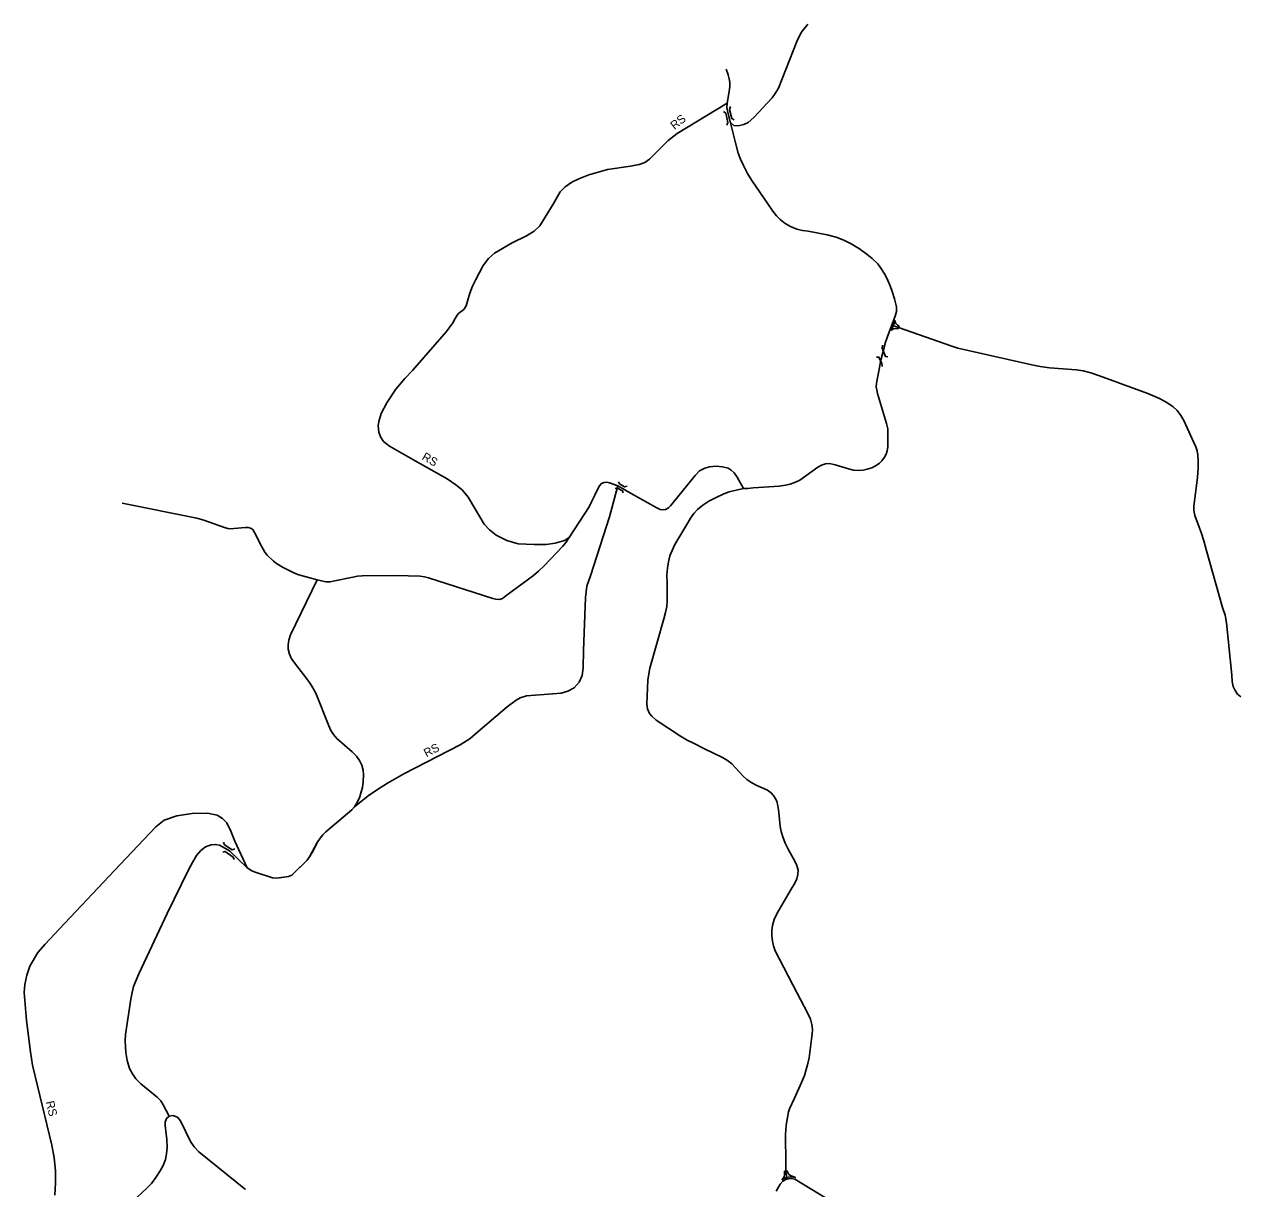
# Model space of a CAD drawing. Extents: x -546703 to -534152, y -1046534 to -1035676.
# Drawn here: x -544992 to -543548, y -1039069 to -1037684 of the extents above; entities that cross this region are included whole.
import ezdxf

# ---------------------------------------------------------------- set-up
doc = ezdxf.new("R2010")
doc.units = 0
for name, color, linetype in [('Vrstva 11', 7, 'Continuous'), ('Vrstva 22', 7, 'Continuous'), ('Vrstva 8', 7, 'Continuous')]:
    doc.layers.add(name, color=color, linetype=linetype)

msp = doc.modelspace()

# ---------------------------------------------------------------- linework, layer by layer
at = {"layer": 'Vrstva 11'}
for points in [[(-544157.7, -1037737), (-544155.1, -1037743.6), (-544153.8, -1037748.4), (-544153.2, -1037752.7), (-544153.2, -1037757.6), (-544154, -1037763.6), (-544156.5, -1037777.6), (-544156.7, -1037782.4), (-544156, -1037786.4), (-544146.4, -1037824.7), (-544143.3, -1037837), (-544140.5, -1037844.1), (-544136.9, -1037851.4), (-544132.1, -1037861.2), (-544127, -1037869.5), (-544108.1, -1037897.3), (-544102.2, -1037905.9), (-544097.7, -1037911.4), (-544093.1, -1037915.9), (-544087.2, -1037920.5), (-544081.2, -1037924.1), (-544073.6, -1037927.1), (-544066.8, -1037928.8), (-544060, -1037929.7), (-544037.5, -1037933.9), (-544026.5, -1037936.7), (-544017.5, -1037940.3), (-544009, -1037944.7), (-543999.1, -1037950.7), (-543989.9, -1037957.4), (-543984, -1037962.2), (-543977.3, -1037968.7), (-543973.5, -1037973.8), (-543968.5, -1037981.6), (-543965.1, -1037988.5), (-543962.5, -1037994.9), (-543960, -1038001.6), (-543957.5, -1038010), (-543955, -1038019.5), (-543955, -1038025.4), (-543956.4, -1038030.9), (-543964.3, -1038052), (-543967.9, -1038061.8), (-543973.8, -1038084.9), (-543975.2, -1038091.9), (-543978.7, -1038110.3), (-543979, -1038115), (-543978.3, -1038118.7), (-543977.5, -1038122.7), (-543966.9, -1038158.4), (-543965.4, -1038164.8), (-543965.1, -1038170.6), (-543965.1, -1038176.8), (-543965.3, -1038186.8), (-543966, -1038190.8), (-543967.4, -1038194.8), (-543969.2, -1038198.4), (-543972.3, -1038202.8), (-543975.2, -1038205.7), (-543979.2, -1038208.4), (-543984.2, -1038211.1), (-543989.9, -1038212.9), (-543994.4, -1038213.8), (-544000.2, -1038214.3), (-544006.2, -1038214), (-544012, -1038212.5), (-544028, -1038207.5), (-544034.5, -1038206.2), (-544039.3, -1038206.6), (-544044.2, -1038208), (-544048.3, -1038210.3), (-544069.8, -1038226), (-544074.9, -1038228.3), (-544081.3, -1038230.6), (-544086.9, -1038232), (-544094.6, -1038233), (-544125.6, -1038235.1), (-544131.9, -1038235.6), (-544137.1, -1038235.9), (-544145.6, -1038237.6), (-544154.1, -1038239.9), (-544160.2, -1038242.2), (-544170.2, -1038246.8), (-544178.1, -1038250.9), (-544185.4, -1038255.5), (-544191.7, -1038260.6), (-544196, -1038265.7), (-544200.1, -1038271.2), (-544203.2, -1038276.8), (-544218.4, -1038302.6), (-544221.9, -1038309.6), (-544224.4, -1038316), (-544226.2, -1038323), (-544227.4, -1038330.4), (-544228.1, -1038338.5), (-544227.8, -1038348.8), (-544227.5, -1038369.7), (-544228.1, -1038376), (-544229.5, -1038383.2), (-544231.7, -1038390.9), (-544248.4, -1038449.6), (-544249.6, -1038456.2), (-544250.5, -1038463.8), (-544251.2, -1038473.5), (-544251.7, -1038492.3), (-544250.9, -1038497.9), (-544248.7, -1038503.3), (-544245.8, -1038506.6), (-544240.6, -1038511.2), (-544212, -1038530.3), (-544203.8, -1038535.1), (-544196.5, -1038538.9), (-544183.4, -1038545.4), (-544162, -1038555.7), (-544156, -1038559.2), (-544150.8, -1038563.4), (-544146.4, -1038568), (-544137.5, -1038578.1), (-544133, -1038581.8), (-544127, -1038586), (-544121, -1038589.1), (-544108.3, -1038594.8), (-544103.8, -1038598.3), (-544100.3, -1038602.3), (-544097.3, -1038607.7), (-544096, -1038613.2), (-544095.3, -1038617.9), (-544094.4, -1038625), (-544093.4, -1038637.8), (-544092.2, -1038643.9), (-544090.1, -1038650.3), (-544087.2, -1038657.7), (-544083.3, -1038665.7), (-544075.8, -1038679.3), (-544073.5, -1038684.3), (-544072, -1038689.7), (-544072.2, -1038694.9), (-544073.6, -1038700), (-544075.9, -1038705.3), (-544080.1, -1038712.3), (-544097, -1038741), (-544100.4, -1038748.7), (-544102.5, -1038755.6), (-544103.2, -1038761.6), (-544103.2, -1038767.4), (-544102.6, -1038774.3), (-544101.4, -1038779.8), (-544099.2, -1038785.8), (-544073.2, -1038836.2), (-544060.7, -1038859.7), (-544057.2, -1038867), (-544055.5, -1038873.4), (-544055, -1038879.2), (-544055.1, -1038885), (-544055.9, -1038891), (-544059, -1038913.2), (-544060.7, -1038921.5), (-544062.2, -1038927.1), (-544064.4, -1038934.1), (-544067.9, -1038942.4), (-544076.4, -1038960.9), (-544082.2, -1038973.7), (-544083.3, -1038977.3), (-544084.6, -1038983.9), (-544086, -1038993), (-544086.9, -1039004.3), (-544086.5, -1039039), (-544086.4, -1039047.8), (-544086, -1039051.6), (-544084.8, -1039056.9)], [(-543960.3, -1038041.5), (-543905.1, -1038060.9), (-543889.3, -1038066.5), (-543881.8, -1038068.9), (-543794.1, -1038088.5), (-543783.9, -1038090.8), (-543772.8, -1038092.4), (-543756.6, -1038093.5), (-543741.2, -1038094.5), (-543732.9, -1038096), (-543723.6, -1038098.2), (-543713.6, -1038101.6), (-543655.9, -1038122.6), (-543642.2, -1038128.7), (-543633.3, -1038133.6), (-543625.9, -1038138.7), (-543621.2, -1038143.1), (-543616.9, -1038149.1), (-543613.3, -1038155), (-543601.5, -1038180.1), (-543599, -1038186.4), (-543597.5, -1038190.8), (-543596.5, -1038196), (-543596, -1038202.9), (-543596, -1038211.1), (-543597, -1038222.7), (-543601.4, -1038257), (-543601.2, -1038262.1), (-543600, -1038268.1), (-543594.9, -1038281.9), (-543592.5, -1038288.3), (-543589.5, -1038298), (-543586.6, -1038308.3), (-543567, -1038377.3), (-543564.1, -1038386.6), (-543562.4, -1038395.5), (-543556, -1038457.7), (-543555.7, -1038465.3), (-543554.3, -1038471.2), (-543552.2, -1038476), (-543549.3, -1038480.3), (-543545.5, -1038483.5)], [(-544876, -1038253.2), (-544787, -1038271.2), (-544778.6, -1038273.6), (-544754.2, -1038282), (-544750.2, -1038283.2), (-544746.6, -1038283.7), (-544743, -1038283.5), (-544729.1, -1038282), (-544726.1, -1038282), (-544723.1, -1038282.8), (-544720.4, -1038284.6), (-544718.7, -1038288.3), (-544710.3, -1038304.3), (-544706.3, -1038311.6), (-544703.4, -1038315.3), (-544696, -1038322.3), (-544692.2, -1038325.2), (-544685.3, -1038329.2), (-544671.1, -1038336.5), (-544665.9, -1038338.5), (-544643.9, -1038344.3), (-544633.5, -1038346.9), (-544628.6, -1038346.8), (-544624.8, -1038346), (-544601.5, -1038341.1), (-544596, -1038340.1), (-544590.5, -1038339.8), (-544548.6, -1038339.1), (-544535.9, -1038339.5), (-544521.4, -1038340.1), (-544516.4, -1038340.9), (-544511.4, -1038342), (-544435.2, -1038366.6), (-544431.5, -1038367.6), (-544427.2, -1038367.8), (-544423.5, -1038366.5), (-544419.4, -1038363.6), (-544386.7, -1038339.1), (-544380.6, -1038334.2), (-544374.1, -1038327.6), (-544351.6, -1038304.3), (-544347.9, -1038299.7), (-544344.1, -1038294.2), (-544320.5, -1038257.5), (-544317.5, -1038251.7), (-544313.8, -1038243.9), (-544308.7, -1038232.9), (-544305.9, -1038230), (-544302.7, -1038228.6), (-544299.5, -1038228.4), (-544296.4, -1038229), (-544286.4, -1038232.7), (-544280.8, -1038235.7), (-544270.6, -1038241.7), (-544240.6, -1038258.3), (-544236, -1038260.8), (-544233.1, -1038261.1), (-544229.5, -1038260.6), (-544226, -1038258.8), (-544223.7, -1038256.5), (-544194.4, -1038220.3), (-544189.2, -1038214.7), (-544183, -1038211.6), (-544177.5, -1038210), (-544169.3, -1038209.3), (-544161.8, -1038210.2), (-544155.3, -1038211.6), (-544151.4, -1038213.9), (-544147.9, -1038217.3), (-544144.3, -1038222.3), (-544137.1, -1038235.9)], [(-544820.1, -1038982.6), (-544827.1, -1038968.9), (-544830.1, -1038964.2), (-544834.3, -1038960), (-544853.6, -1038943.9), (-544859.6, -1038938.1), (-544863.8, -1038932.1), (-544867.1, -1038925.6), (-544869.8, -1038916.4), (-544871.4, -1038906.9), (-544872, -1038900.1), (-544872.3, -1038893), (-544871.8, -1038885.5), (-544865.8, -1038843.4), (-544864.2, -1038835.2), (-544862.3, -1038828.4), (-544859.3, -1038820.5), (-544855.9, -1038813.2), (-544822.5, -1038741.4), (-544797.1, -1038689.5), (-544792.4, -1038680.8), (-544787.4, -1038672.4), (-544782.5, -1038666.6), (-544776.7, -1038662.2), (-544770.2, -1038659.6), (-544765.3, -1038659.2), (-544760.2, -1038660.1), (-544749.5, -1038665.9), (-544747.8, -1038667.3), (-544727.1, -1038687.2), (-544721.6, -1038690.6), (-544716.6, -1038692.8), (-544697.1, -1038699), (-544692.4, -1038699.5), (-544686.1, -1038698.6), (-544678, -1038697.5), (-544674, -1038695.7), (-544670.5, -1038692.3), (-544656, -1038678.1), (-544653.1, -1038673.8), (-544648.9, -1038666.9), (-544643.8, -1038657.1), (-544640.3, -1038651.6), (-544637.4, -1038647.8), (-544633.6, -1038644.1), (-544602.9, -1038617.9), (-544599.4, -1038614.4), (-544597.1, -1038610.7), (-544593.7, -1038603.6), (-544591.6, -1038596.8), (-544590.2, -1038591.4), (-544589.1, -1038584.8), (-544588.9, -1038576.6), (-544589.4, -1038570.9), (-544591, -1038564.9), (-544593.5, -1038559.5), (-544597.1, -1038554.4), (-544602.2, -1038549.2), (-544620.6, -1038533), (-544624.7, -1038528.6), (-544627.6, -1038523.8), (-544630.3, -1038518.3), (-544645.7, -1038479.2), (-544649, -1038473.1), (-544652.2, -1038467.6), (-544656.1, -1038462.3), (-544667, -1038448.3), (-544674.4, -1038438.5), (-544676.9, -1038432.9), (-544678.5, -1038427.1), (-544678.5, -1038421.6), (-544677.6, -1038416.1), (-544675.6, -1038409.7), (-544643.9, -1038344.3)], [(-544729.4, -1039069.9), (-544784.9, -1039024.7), (-544790.4, -1039019.1), (-544794.6, -1039012.8), (-544806.5, -1038988.2), (-544810.2, -1038983.7), (-544815.7, -1038981.8), (-544820.1, -1038982.6), (-544823.1, -1038985.2), (-544824.6, -1038989.8), (-544824.6, -1038993.7), (-544822.8, -1039010.3), (-544822.2, -1039019.8), (-544823, -1039027.1), (-544824.5, -1039034), (-544827.3, -1039041.1), (-544830.6, -1039047.5), (-544835.8, -1039055.6), (-544841.2, -1039062.6), (-544846.8, -1039068.5), (-544869.2, -1039089)], [(-544008, -1039098.7), (-544075.9, -1039057.3), (-544080.3, -1039056.6), (-544085.8, -1039057.6), (-544090.1, -1039059.9), (-544093.2, -1039063.3), (-544098.2, -1039071.8)]]:
    msp.add_lwpolyline(points, dxfattribs=at)
for points in [[(-543958.7, -1038042), (-543960.7, -1038047.5), (-543959.6, -1038046.6), (-543958.6, -1038046), (-543957.6, -1038045.7), (-543955.8, -1038045.5), (-543953.2, -1038045.8), (-543951.9, -1038042.6), (-543953.8, -1038041.6), (-543955, -1038040.5), (-543955.7, -1038039.4), (-543956.2, -1038038), (-543956.6, -1038036.3)], [(-544091.4, -1039058.3), (-544089.2, -1039055.9), (-544088.4, -1039054.5), (-544088, -1039052.1), (-544088.1, -1039047.9), (-544084.6, -1039047.7), (-544084.2, -1039050), (-544083.1, -1039051.8), (-544080.9, -1039053.2), (-544075.1, -1039055.4), (-544080.3, -1039054.5), (-544086.5, -1039055.6)]]:
    msp.add_lwpolyline(points, close=True, dxfattribs=at)
at = {"layer": 'Vrstva 22'}
for points in [[(-544286.4, -1038232.7), (-544296.4, -1038229), (-544299.5, -1038228.4), (-544302.7, -1038228.6), (-544305.9, -1038230), (-544308.7, -1038232.9), (-544313.8, -1038243.9), (-544317.5, -1038251.7), (-544320.5, -1038257.5), (-544344.1, -1038294.2), (-544350, -1038297.7), (-544360.9, -1038301), (-544371.8, -1038302.4), (-544385.8, -1038302.6), (-544404.9, -1038301.6), (-544418.2, -1038297.7), (-544431, -1038291.5), (-544439.2, -1038284.9), (-544445.3, -1038278.4), (-544455.8, -1038260.9), (-544464.2, -1038246.1), (-544471.4, -1038237.5), (-544479, -1038231.5), (-544489.5, -1038224.3), (-544527.3, -1038202.7), (-544558.1, -1038185.5), (-544565.1, -1038179.7), (-544568.8, -1038174.2), (-544570.6, -1038168.6), (-544571.5, -1038161.2), (-544570.8, -1038156.1), (-544568, -1038146.6), (-544561, -1038133.7), (-544550.3, -1038117.8), (-544539.6, -1038104.9), (-544530.6, -1038095.6), (-544490.3, -1038049.2), (-544482.7, -1038038.9), (-544479.9, -1038033.6), (-544477.6, -1038029.5), (-544475.3, -1038027.2), (-544469.6, -1038022.7), (-544466.7, -1038018.6), (-544465.3, -1038013), (-544462.4, -1038003.6), (-544459.1, -1037995.1), (-544455.4, -1037987.3), (-544446.4, -1037970.7), (-544440.2, -1037962.1), (-544433.2, -1037955.7), (-544412.1, -1037943.4), (-544395, -1037935.1), (-544386, -1037929.6), (-544379, -1037923.4), (-544363.2, -1037897.5), (-544355, -1037882.9), (-544349, -1037877), (-544341, -1037871.4), (-544332.8, -1037867.3), (-544320.7, -1037862.6), (-544298.5, -1037856.4), (-544271.2, -1037852.3), (-544260.9, -1037850.5), (-544254.1, -1037848), (-544248.8, -1037844.1), (-544244, -1037839.2), (-544226.4, -1037821.9), (-544215.7, -1037813.3), (-544156.5, -1037777.6), (-544156.7, -1037782.4), (-544156, -1037786.4), (-544152.6, -1037800), (-544148.5, -1037803.8), (-544143.4, -1037804.4), (-544136.4, -1037802.8), (-544131.5, -1037800.3), (-544124.7, -1037794.6), (-544102.9, -1037771.1), (-544099.2, -1037766), (-544095.1, -1037759.4), (-544073.4, -1037703.9), (-544068.2, -1037693.4), (-544060.2, -1037683.6)], [(-544956.1, -1039076.5), (-544955.4, -1039061.7), (-544955.1, -1039047.3), (-544956.7, -1039032.2), (-544959.6, -1039016.8), (-544976.6, -1038946.4), (-544982.4, -1038921.7), (-544985, -1038906), (-544989.8, -1038868.7), (-544992.3, -1038835.3), (-544991.7, -1038825.7), (-544989.4, -1038814.8), (-544985.6, -1038803.9), (-544976.3, -1038787.8), (-544967.6, -1038777.8), (-544950.9, -1038760.2), (-544878.4, -1038683.1), (-544836, -1038638.1), (-544825.8, -1038630.4), (-544811, -1038625.3), (-544792.7, -1038622.4), (-544774.4, -1038622.1), (-544762.9, -1038624.3), (-544756.4, -1038628.2), (-544751.6, -1038633.7), (-544746.5, -1038643.3), (-544742, -1038655.5), (-544727.1, -1038687.2), (-544721.6, -1038690.6), (-544716.6, -1038692.8), (-544697.1, -1038699), (-544692.4, -1038699.5), (-544678, -1038697.5), (-544674, -1038695.7), (-544656, -1038678.1), (-544653.1, -1038673.8), (-544643.8, -1038657.1), (-544640.3, -1038651.6), (-544637.4, -1038647.8), (-544633.6, -1038644.1), (-544602.9, -1038617.9), (-544599.4, -1038614.4), (-544583.4, -1038601.4), (-544572.1, -1038593.8), (-544560.4, -1038586.2), (-544541.1, -1038575.3), (-544473.9, -1038540.6), (-544462.2, -1038533), (-544455.8, -1038527.5), (-544418, -1038495.4), (-544407.1, -1038487.4), (-544402.4, -1038484.7), (-544395.2, -1038482.5), (-544363.8, -1038480.2), (-544353.7, -1038479.2), (-544345.7, -1038476.9), (-544338.5, -1038472.8), (-544332.2, -1038466.2), (-544328.7, -1038458.4), (-544327.6, -1038449.2), (-544327.4, -1038428.4), (-544325, -1038365.3), (-544323.1, -1038351.9), (-544318.8, -1038339.8), (-544296.4, -1038269.7), (-544286.4, -1038232.7)]]:
    msp.add_lwpolyline(points, dxfattribs=at)
at = {"layer": 'Vrstva 8'}
for points in [[(-544152.5, -1037781.4), (-544153.5, -1037784.8), (-544150.7, -1037795.7), (-544148, -1037797.3)], [(-544160.8, -1037787.3), (-544158.1, -1037789.3), (-544155.5, -1037800.5), (-544156.8, -1037803.6)], [(-543971.7, -1038065.3), (-543971.8, -1038068.7), (-543968.2, -1038078.6), (-543965.4, -1038079)], [(-543978.6, -1038079.6), (-543975.8, -1038079.5), (-543972.3, -1038087.1), (-543972.1, -1038090.5)], [(-544285.5, -1038227.8), (-544284.4, -1038230.3), (-544278.3, -1038233.9), (-544275.3, -1038233.2)], [(-544289.5, -1038235.9), (-544286.9, -1038235.4), (-544280.8, -1038238.7), (-544279.9, -1038241.1)], [(-544755.4, -1038656.5), (-544754.2, -1038659.5), (-544744.9, -1038665.6), (-544742.1, -1038664.3)], [(-544756.1, -1038668.5), (-544753.3, -1038667.6), (-544744, -1038674.4), (-544742.6, -1038677.3)]]:
    msp.add_lwpolyline(points, dxfattribs=at)

# ---------------------------------------------------------------- texts
at = {"layer": 'Vrstva 22'}
for rotation, p in [(38.9441, (-544218.9, -1037809.4)), (330.2741, (-544520.3, -1038200.9)), (27.3446, (-544514, -1038555.7)), (283.5968, (-544966.9, -1038965.5))]:
    msp.add_text('RS', height=10, rotation=rotation, dxfattribs=at).set_placement(p)

doc.saveas('drawing.dxf')
